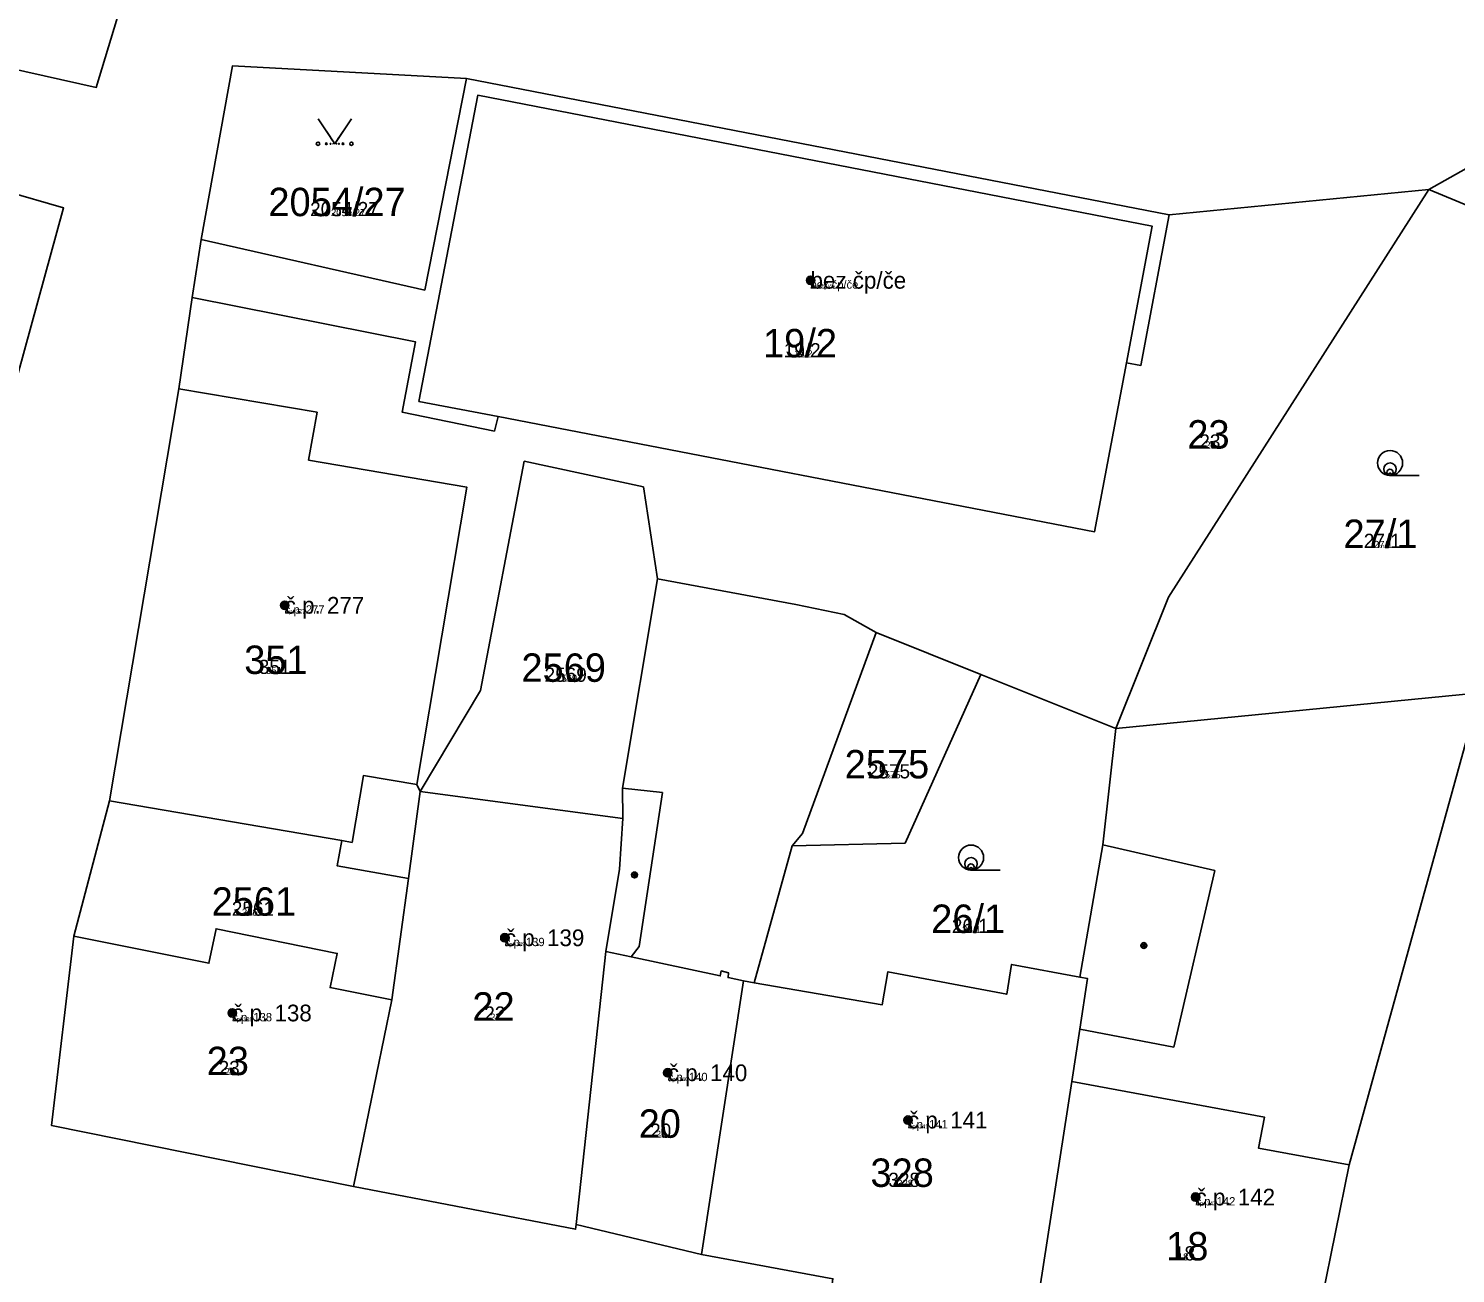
# Model space of a CAD drawing. Extents: x -744652 to -739090, y -980828 to -975855.
# Drawn here: x -742512.8 to -742427.4, y -978597.9 to -978523.4 of the extents above; entities that cross this region are included whole.
import ezdxf

# ---------------------------------------------------------------- set-up
doc = ezdxf.new("R2010")
doc.units = 0
for name, color, linetype in [('KAT_02_hranice parcel', 7, 'Continuous'), ('KAT_03_1000_st čísla parcelní', 7, 'Continuous'), ('KAT_03_1000_čísla parcelní', 7, 'Continuous'), ('KAT_03_1000_čísla popisná', 7, 'Continuous'), ('KAT_03_100_st čísla parcelní', 7, 'Continuous'), ('KAT_03_100_čísla parcelní', 7, 'Continuous'), ('KAT_03_100_čísla popisná', 7, 'Continuous'), ('KAT_03_250_st čísla parcelní', 7, 'Continuous'), ('KAT_03_250_čísla parcelní', 7, 'Continuous'), ('KAT_03_250_čísla popisná', 7, 'Continuous'), ('KAT_03_500_st čísla parcelní', 7, 'Continuous'), ('KAT_03_500_čísla parcelní', 7, 'Continuous'), ('KAT_03_500_čísla popisná', 7, 'Continuous'), ('KAT_04_vnitřní kresba', 7, 'Continuous'), ('KAT_05_1000_značky kultur', 7, 'Continuous'), ('KAT_05_100_značky kultur', 7, 'Continuous'), ('KAT_05_250_značky kultur', 7, 'Continuous'), ('KAT_05_500_značky kultur', 7, 'Continuous'), ('KAT_07_1000_značky budov', 7, 'Continuous'), ('KAT_07_100_značky budov', 7, 'Continuous'), ('KAT_07_500_značky budov', 7, 'Continuous'), ('KAT_14_plocha_budovy', 7, 'Continuous')]:
    doc.layers.add(name, color=color, linetype=linetype)

msp = doc.modelspace()

# ---------------------------------------------------------------- linework, layer by layer
at = {"layer": 'KAT_02_hranice parcel'}
for p, q in [((-742486.59, -978526.39), (-742444.56, -978534.56)), ((-742429.01, -978533.04), (-742421.31, -978528.7)), ((-742444.56, -978534.56), (-742429.01, -978533.04)), ((-742429.01, -978533.04), (-742420.61, -978536.53)), ((-742503.01, -978539.5), (-742502.47, -978536.03)), ((-742503.8, -978544.97), (-742503.01, -978539.5)), ((-742507.95, -978569.63), (-742503.8, -978544.97)), ((-742462.08, -978559.55), (-742455.82, -978562.06)), ((-742455.82, -978562.06), (-742447.74, -978565.29)), ((-742425.99, -978563.15), (-742447.74, -978565.29)), ((-742489.36, -978569.06), (-742490.07, -978574.27)), ((-742477.25, -978570.68), (-742489.36, -978569.06)), ((-742510.08, -978577.72), (-742507.95, -978569.63)), ((-742469.39, -978580.51), (-742467.11, -978572.32)), ((-742490.07, -978574.27), (-742491.06, -978581.54)), ((-742491.06, -978581.54), (-742493.35, -978592.71)), ((-742472.53, -978596.77), (-742480.04, -978594.97))]:
    msp.add_line(p, q, dxfattribs=at)
for points in [[(-742504.65, -978513.37), (-742508.75, -978526.92), (-742531.88, -978521.75), (-742534.32, -978519.68)], [(-742502.47, -978536.03), (-742500.6, -978525.64), (-742486.59, -978526.39)], [(-742486.59, -978526.39), (-742489.09, -978539.05), (-742502.47, -978536.03)], [(-742527.99, -978529.15), (-742510.7, -978534.14), (-742514.17, -978546.79)], [(-742447.74, -978565.29), (-742444.6, -978557.43), (-742429.01, -978533.04)], [(-742503.01, -978539.5), (-742489.65, -978542.15), (-742490.44, -978546.37), (-742484.92, -978547.49), (-742484.7, -978546.63), (-742449.01, -978553.52), (-742447.1, -978543.4), (-742446.24, -978543.56), (-742444.56, -978534.56)], [(-742489.36, -978569.06), (-742489.57, -978568.65), (-742486.57, -978550.85), (-742496.04, -978549.23), (-742495.53, -978546.37), (-742503.8, -978544.97)], [(-742489.36, -978569.06), (-742485.76, -978563.01), (-742483.14, -978549.3), (-742476.01, -978550.83), (-742475.16, -978556.33)], [(-742475.16, -978556.33), (-742477.27, -978568.86), (-742477.25, -978570.68)], [(-742462.08, -978559.55), (-742464, -978558.47), (-742466.88, -978557.88), (-742475.16, -978556.33)], [(-742467.11, -978572.32), (-742466.49, -978571.57), (-742462.08, -978559.55)], [(-742455.82, -978562.06), (-742460.35, -978572.15), (-742467.11, -978572.32)], [(-742436.23, -978603.49), (-742433.78, -978591.41), (-742425.99, -978563.15)], [(-742447.74, -978565.29), (-742448.52, -978572.26), (-742449.9, -978580.17)], [(-742507.95, -978569.63), (-742494.06, -978572), (-742494.34, -978573.51), (-742490.07, -978574.27)], [(-742477.25, -978570.68), (-742477.43, -978573.72), (-742478.25, -978578.64), (-742480.04, -978594.97)], [(-742493.35, -978592.71), (-742511.43, -978589.05), (-742510.08, -978577.72)], [(-742491.06, -978581.54), (-742494.76, -978580.8), (-742494.33, -978578.76), (-742501.58, -978577.28), (-742502.01, -978579.34), (-742510.08, -978577.72)], [(-742449.9, -978580.17), (-742453.98, -978579.41), (-742454.27, -978581.2), (-742461.38, -978579.85), (-742461.72, -978581.83), (-742469.39, -978580.51)], [(-742449.9, -978580.17), (-742449.43, -978580.26), (-742449.9, -978583.28), (-742450.38, -978586.43), (-742452.55, -978600.47)], [(-742472.53, -978596.77), (-742470.03, -978580.4), (-742469.39, -978580.51)], [(-742480.04, -978594.97), (-742480.07, -978595.26), (-742493.35, -978592.71)], [(-742452.55, -978600.47), (-742460.38, -978599.02), (-742460.45, -978599.49), (-742464.74, -978598.7), (-742464.67, -978598.23), (-742472.53, -978596.77)]]:
    msp.add_lwpolyline(points, dxfattribs=at)
at = {"layer": 'KAT_03_1000_čísla popisná'}
for centre in [(-742466.01, -978538.47), (-742466.01, -978538.47), (-742497.47, -978557.92), (-742497.47, -978557.92), (-742484.3, -978577.82), (-742484.3, -978577.82), (-742500.61, -978582.32), (-742500.61, -978582.32), (-742474.55, -978585.9), (-742474.55, -978585.9), (-742460.18, -978588.73), (-742460.18, -978588.73), (-742442.97, -978593.34), (-742442.97, -978593.34)]:
    msp.add_circle(centre, 0.25, dxfattribs=at)
at = {"layer": 'KAT_03_100_čísla popisná'}
for centre in [(-742466.01, -978538.47), (-742466.01, -978538.47), (-742497.47, -978557.92), (-742497.47, -978557.92), (-742484.3, -978577.82), (-742484.3, -978577.82), (-742500.61, -978582.32), (-742500.61, -978582.32), (-742474.55, -978585.9), (-742474.55, -978585.9), (-742460.18, -978588.73), (-742460.18, -978588.73), (-742442.97, -978593.34), (-742442.97, -978593.34)]:
    msp.add_circle(centre, 0.025, dxfattribs=at)
at = {"layer": 'KAT_03_250_čísla popisná'}
for centre in [(-742466.01, -978538.47), (-742466.01, -978538.47), (-742497.47, -978557.92), (-742497.47, -978557.92), (-742484.3, -978577.82), (-742484.3, -978577.82), (-742500.61, -978582.32), (-742500.61, -978582.32), (-742474.55, -978585.9), (-742474.55, -978585.9), (-742460.18, -978588.73), (-742460.18, -978588.73), (-742442.97, -978593.34), (-742442.97, -978593.34)]:
    msp.add_circle(centre, 0.0625, dxfattribs=at)
at = {"layer": 'KAT_03_500_čísla popisná'}
for centre in [(-742466.01, -978538.47), (-742466.01, -978538.47), (-742497.47, -978557.92), (-742497.47, -978557.92), (-742484.3, -978577.82), (-742484.3, -978577.82), (-742500.61, -978582.32), (-742500.61, -978582.32), (-742474.55, -978585.9), (-742474.55, -978585.9), (-742460.18, -978588.73), (-742460.18, -978588.73), (-742442.97, -978593.34), (-742442.97, -978593.34)]:
    msp.add_circle(centre, 0.125, dxfattribs=at)
at = {"layer": 'KAT_04_vnitřní kresba'}
for p, q in [((-742489.44, -978545.72), (-742485.92, -978527.39)), ((-742485.92, -978527.39), (-742445.56, -978535.23)), ((-742445.56, -978535.23), (-742447.1, -978543.4)), ((-742484.7, -978546.63), (-742489.44, -978545.72)), ((-742492.76, -978568.11), (-742493.44, -978572.11)), ((-742489.57, -978568.65), (-742492.76, -978568.11)), ((-742477.27, -978568.86), (-742474.87, -978569.12)), ((-742474.87, -978569.12), (-742476.26, -978578.35)), ((-742493.44, -978572.11), (-742494.06, -978572)), ((-742441.81, -978573.79), (-742448.52, -978572.26)), ((-742444.27, -978584.36), (-742441.81, -978573.79)), ((-742476.26, -978578.35), (-742476.75, -978578.96)), ((-742478.25, -978578.64), (-742476.75, -978578.96)), ((-742476.75, -978578.96), (-742471.41, -978580.1)), ((-742471.41, -978580.1), (-742471.35, -978579.8)), ((-742471.35, -978579.8), (-742470.91, -978579.92)), ((-742470.91, -978579.92), (-742470.94, -978580.2)), ((-742470.94, -978580.2), (-742470.03, -978580.4)), ((-742449.9, -978583.28), (-742444.27, -978584.36)), ((-742450.38, -978586.43), (-742438.84, -978588.56)), ((-742438.84, -978588.56), (-742439.21, -978590.41)), ((-742439.21, -978590.41), (-742433.78, -978591.41))]:
    msp.add_line(p, q, dxfattribs=at)
at = {"layer": 'KAT_05_1000_značky kultur'}
for p, q in [((-742431.333, -978550.15), (-742429.583, -978550.15)), ((-742456.403, -978573.77), (-742454.653, -978573.77))]:
    msp.add_line(p, q, dxfattribs=at)
msp.add_lwpolyline([(-742495.48, -978528.799), (-742494.48, -978530.3), (-742493.48, -978528.799)], dxfattribs=at)
for centre, radius in [((-742495.48, -978530.299), 0.1), ((-742493.48, -978530.299), 0.1), ((-742431.333, -978549.4), 0.75), ((-742456.403, -978573.02), 0.75)]:
    msp.add_circle(centre, radius, dxfattribs=at)
at = {"layer": 'KAT_05_100_značky kultur'}
for p, q in [((-742431.339, -978550.15), (-742431.164, -978550.15)), ((-742456.409, -978573.77), (-742456.234, -978573.77))]:
    msp.add_line(p, q, dxfattribs=at)
msp.add_lwpolyline([(-742494.58, -978530.15), (-742494.48, -978530.3), (-742494.38, -978530.15)], dxfattribs=at)
for centre, radius in [((-742494.58, -978530.3), 0.01), ((-742494.38, -978530.3), 0.01), ((-742431.339, -978550.075), 0.075), ((-742456.409, -978573.695), 0.075)]:
    msp.add_circle(centre, radius, dxfattribs=at)
at = {"layer": 'KAT_05_250_značky kultur'}
for p, q in [((-742431.338, -978550.15), (-742430.901, -978550.15)), ((-742456.408, -978573.77), (-742455.971, -978573.77))]:
    msp.add_line(p, q, dxfattribs=at)
msp.add_lwpolyline([(-742494.73, -978529.925), (-742494.48, -978530.3), (-742494.23, -978529.925)], dxfattribs=at)
for centre, radius in [((-742494.73, -978530.3), 0.025), ((-742494.23, -978530.3), 0.025), ((-742431.338, -978549.962), 0.187), ((-742456.408, -978573.582), 0.187)]:
    msp.add_circle(centre, radius, dxfattribs=at)
at = {"layer": 'KAT_05_500_značky kultur'}
for p, q in [((-742431.336, -978550.15), (-742430.461, -978550.15)), ((-742456.407, -978573.77), (-742455.532, -978573.77))]:
    msp.add_line(p, q, dxfattribs=at)
msp.add_lwpolyline([(-742494.98, -978529.549), (-742494.48, -978530.3), (-742493.98, -978529.549)], dxfattribs=at)
for centre, radius in [((-742494.98, -978530.3), 0.05), ((-742493.98, -978530.3), 0.05), ((-742431.336, -978549.775), 0.375), ((-742456.406, -978573.395), 0.375)]:
    msp.add_circle(centre, radius, dxfattribs=at)
at = {"layer": 'KAT_07_1000_značky budov'}
for centre in [(-742466.017, -978538.469), (-742497.477, -978557.919), (-742476.537, -978574.059), (-742484.307, -978577.819), (-742446.067, -978578.279), (-742500.617, -978582.319), (-742474.557, -978585.899), (-742460.187, -978588.729), (-742442.977, -978593.339)]:
    msp.add_circle(centre, 0.175, dxfattribs=at)
at = {"layer": 'KAT_07_100_značky budov'}
for centre in [(-742466.011, -978538.47), (-742497.471, -978557.92), (-742476.531, -978574.06), (-742484.301, -978577.82), (-742446.061, -978578.28), (-742500.611, -978582.32), (-742474.551, -978585.9), (-742460.181, -978588.73), (-742442.971, -978593.34)]:
    msp.add_circle(centre, 0.0175, dxfattribs=at)
at = {"layer": 'KAT_07_500_značky budov'}
for centre, radius in [((-742466.013, -978538.47), 0.0875), ((-742466.012, -978538.47), 0.0438), ((-742497.473, -978557.92), 0.0875), ((-742497.472, -978557.92), 0.0438), ((-742476.533, -978574.06), 0.0875), ((-742476.532, -978574.06), 0.0438), ((-742484.303, -978577.82), 0.0875), ((-742484.302, -978577.82), 0.0438), ((-742446.063, -978578.28), 0.0875), ((-742446.062, -978578.28), 0.0438), ((-742500.613, -978582.32), 0.0875), ((-742500.612, -978582.32), 0.0438), ((-742474.553, -978585.9), 0.0875), ((-742474.552, -978585.9), 0.0438), ((-742460.183, -978588.73), 0.0875), ((-742460.182, -978588.73), 0.0438), ((-742442.973, -978593.34), 0.0875), ((-742442.972, -978593.34), 0.0438)]:
    msp.add_circle(centre, radius, dxfattribs=at)
at = {"layer": 'KAT_14_plocha_budovy'}
for points in [[(-742489.44, -978545.72), (-742484.7, -978546.63), (-742449.01, -978553.52), (-742447.1, -978543.4), (-742445.56, -978535.23), (-742485.92, -978527.39)], [(-742531.55, -978541.72), (-742514.17, -978546.79), (-742510.7, -978534.14), (-742527.99, -978529.15)], [(-742507.95, -978569.63), (-742494.06, -978572), (-742493.44, -978572.11), (-742492.76, -978568.11), (-742489.57, -978568.65), (-742486.57, -978550.85), (-742496.04, -978549.23), (-742495.53, -978546.37), (-742503.8, -978544.97)], [(-742493.35, -978592.71), (-742480.07, -978595.26), (-742480.04, -978594.97), (-742478.25, -978578.64), (-742477.43, -978573.72), (-742477.25, -978570.68), (-742489.36, -978569.06), (-742490.07, -978574.27), (-742491.06, -978581.54)], [(-742510.08, -978577.72), (-742511.43, -978589.05), (-742493.35, -978592.71), (-742491.06, -978581.54), (-742494.76, -978580.8), (-742494.33, -978578.76), (-742501.58, -978577.28), (-742502.01, -978579.34)], [(-742478.25, -978578.64), (-742480.04, -978594.97), (-742472.53, -978596.77), (-742470.03, -978580.4), (-742470.94, -978580.2), (-742470.91, -978579.92), (-742471.35, -978579.8), (-742471.41, -978580.1), (-742476.75, -978578.96)], [(-742460.38, -978599.02), (-742452.55, -978600.47), (-742450.38, -978586.43), (-742449.9, -978583.28), (-742449.43, -978580.26), (-742449.9, -978580.17), (-742453.98, -978579.41), (-742454.27, -978581.2), (-742461.38, -978579.85), (-742461.72, -978581.83), (-742469.39, -978580.51), (-742470.03, -978580.4), (-742472.53, -978596.77), (-742464.67, -978598.23), (-742464.74, -978598.7), (-742460.45, -978599.49)], [(-742450.38, -978586.43), (-742452.55, -978600.47), (-742449, -978601.11), (-742449.01, -978601.26), (-742439.96, -978602.96), (-742439.93, -978602.79), (-742436.23, -978603.49), (-742433.78, -978591.41), (-742439.21, -978590.41), (-742438.84, -978588.56)]]:
    msp.add_lwpolyline(points, close=True, dxfattribs=at)

# ---------------------------------------------------------------- texts
at = {"layer": 'KAT_03_1000_st čísla parcelní'}
for s, p in [('19/2', (-742468.851, -978543.08)), ('351', (-742499.894, -978562.03)), ('22', (-742486.242, -978582.78)), ('23', (-742502.142, -978586.04)), ('20', (-742476.292, -978589.79)), ('328', (-742462.424, -978592.73)), ('18', (-742444.732, -978597.13))]:
    msp.add_text(s, height=1.7, dxfattribs=at).set_placement(p)
at = {"layer": 'KAT_03_1000_čísla parcelní'}
for s, p in [('2054/27', (-742498.448, -978534.63)), ('23', (-742443.462, -978548.54)), ('27/1', (-742434.121, -978554.49)), ('2569', (-742483.307, -978562.5)), ('2575', (-742463.967, -978568.28)), ('2561', (-742501.847, -978576.5)), ('26/1', (-742458.791, -978577.53))]:
    msp.add_text(s, height=1.7, dxfattribs=at).set_placement(p)
at = {"layer": 'KAT_03_1000_čísla popisná'}
for s, height, p in [('bez čp/če', 1, (-742466.01, -978538.97)), ('19/2', 0.017, (-742466.406, -978543.08)), ('č.p. 277', 1, (-742497.47, -978558.42)), ('351', 0.017, (-742498.171, -978562.03)), ('č.p. 139', 1, (-742484.3, -978578.32)), ('č.p. 138', 1, (-742500.61, -978582.82)), ('22', 0.017, (-742484.844, -978582.78)), ('č.p. 140', 1, (-742474.55, -978586.4)), ('23', 0.017, (-742500.731, -978586.04)), ('č.p. 141', 1, (-742460.18, -978589.23)), ('20', 0.017, (-742474.94, -978589.79)), ('328', 0.017, (-742460.31, -978592.73)), ('č.p. 142', 1, (-742442.97, -978593.84)), ('18', 0.017, (-742443.804, -978597.13))]:
    msp.add_text(s, height=height, dxfattribs=at).set_placement(p)
at = {"layer": 'KAT_03_100_st čísla parcelní'}
for s, p in [('19/2', (-742466.628, -978543.08)), ('351', (-742498.328, -978562.03)), ('22', (-742484.971, -978582.78)), ('23', (-742500.859, -978586.04)), ('20', (-742475.063, -978589.79)), ('328', (-742460.503, -978592.73)), ('18', (-742443.889, -978597.13))]:
    msp.add_text(s, height=0.17, dxfattribs=at).set_placement(p)
at = {"layer": 'KAT_03_100_čísla parcelní'}
for s, p in [('2054/27', (-742493.955, -978534.63)), ('23', (-742442.179, -978548.54)), ('27/1', (-742431.935, -978554.49)), ('2569', (-742480.819, -978562.5)), ('2575', (-742461.473, -978568.28)), ('2561', (-742499.673, -978576.5)), ('26/1', (-742456.568, -978577.53))]:
    msp.add_text(s, height=0.17, dxfattribs=at).set_placement(p)
at = {"layer": 'KAT_03_100_čísla popisná'}
for s, height, p in [('bez čp/če', 0.1, (-742466.01, -978538.97)), ('19/2', 0.0017, (-742466.384, -978543.08)), ('č.p. 277', 0.1, (-742497.47, -978558.42)), ('351', 0.0017, (-742498.156, -978562.03)), ('č.p. 139', 0.1, (-742484.3, -978578.32)), ('č.p. 138', 0.1, (-742500.61, -978582.82)), ('22', 0.0017, (-742484.831, -978582.78)), ('23', 0.0017, (-742500.718, -978586.04)), ('č.p. 140', 0.1, (-742474.55, -978586.4)), ('č.p. 141', 0.1, (-742460.18, -978589.23)), ('20', 0.0017, (-742474.928, -978589.79)), ('328', 0.0017, (-742460.291, -978592.73)), ('č.p. 142', 0.1, (-742442.97, -978593.84)), ('18', 0.0017, (-742443.796, -978597.13))]:
    msp.add_text(s, height=height, dxfattribs=at).set_placement(p)
at = {"layer": 'KAT_03_250_st čísla parcelní'}
for s, p in [('19/2', (-742466.999, -978543.08)), ('351', (-742498.589, -978562.03)), ('22', (-742485.183, -978582.78)), ('23', (-742501.073, -978586.04)), ('20', (-742475.268, -978589.79)), ('328', (-742460.823, -978592.73)), ('18', (-742444.029, -978597.13))]:
    msp.add_text(s, height=0.425, dxfattribs=at).set_placement(p)
at = {"layer": 'KAT_03_250_čísla parcelní'}
for s, p in [('2054/27', (-742494.704, -978534.63)), ('23', (-742442.393, -978548.54)), ('27/1', (-742432.299, -978554.49)), ('2569', (-742481.234, -978562.5)), ('2575', (-742461.889, -978568.28)), ('2561', (-742500.035, -978576.5)), ('26/1', (-742456.939, -978577.53))]:
    msp.add_text(s, height=0.425, dxfattribs=at).set_placement(p)
at = {"layer": 'KAT_03_250_čísla popisná'}
for s, height, p in [('bez čp/če', 0.25, (-742466.01, -978538.97)), ('19/2', 0.00425, (-742466.388, -978543.08)), ('č.p. 277', 0.25, (-742497.47, -978558.42)), ('351', 0.00425, (-742498.158, -978562.03)), ('č.p. 139', 0.25, (-742484.3, -978578.32)), ('č.p. 138', 0.25, (-742500.61, -978582.82)), ('22', 0.00425, (-742484.833, -978582.78)), ('23', 0.00425, (-742500.72, -978586.04)), ('č.p. 140', 0.25, (-742474.55, -978586.4)), ('č.p. 141', 0.25, (-742460.18, -978589.23)), ('20', 0.00425, (-742474.93, -978589.79)), ('328', 0.00425, (-742460.294, -978592.73)), ('č.p. 142', 0.25, (-742442.97, -978593.84)), ('18', 0.00425, (-742443.797, -978597.13))]:
    msp.add_text(s, height=height, dxfattribs=at).set_placement(p)
at = {"layer": 'KAT_03_500_st čísla parcelní'}
for s, p in [('19/2', (-742467.616, -978543.08)), ('351', (-742499.024, -978562.03)), ('22', (-742485.536, -978582.78)), ('23', (-742501.429, -978586.04)), ('20', (-742475.609, -978589.79)), ('328', (-742461.357, -978592.73)), ('18', (-742444.264, -978597.13))]:
    msp.add_text(s, height=0.85, dxfattribs=at).set_placement(p)
at = {"layer": 'KAT_03_500_čísla parcelní'}
for s, p in [('2054/27', (-742495.952, -978534.63)), ('23', (-742442.749, -978548.54)), ('27/1', (-742432.906, -978554.49)), ('2569', (-742481.925, -978562.5)), ('2575', (-742462.582, -978568.28)), ('2561', (-742500.639, -978576.5)), ('26/1', (-742457.556, -978577.53))]:
    msp.add_text(s, height=0.85, dxfattribs=at).set_placement(p)
at = {"layer": 'KAT_03_500_čísla popisná'}
for s, height, p in [('bez čp/če', 0.5, (-742466.01, -978538.97)), ('19/2', 0.0085, (-742466.394, -978543.08)), ('č.p. 277', 0.5, (-742497.47, -978558.42)), ('351', 0.0085, (-742498.163, -978562.03)), ('č.p. 139', 0.5, (-742484.3, -978578.32)), ('č.p. 138', 0.5, (-742500.61, -978582.82)), ('22', 0.0085, (-742484.837, -978582.78)), ('23', 0.0085, (-742500.724, -978586.04)), ('č.p. 140', 0.5, (-742474.55, -978586.4)), ('č.p. 141', 0.5, (-742460.18, -978589.23)), ('20', 0.0085, (-742474.934, -978589.79)), ('328', 0.0085, (-742460.3, -978592.73)), ('č.p. 142', 0.5, (-742442.97, -978593.84)), ('18', 0.0085, (-742443.8, -978597.13))]:
    msp.add_text(s, height=height, dxfattribs=at).set_placement(p)

doc.saveas('drawing.dxf')
